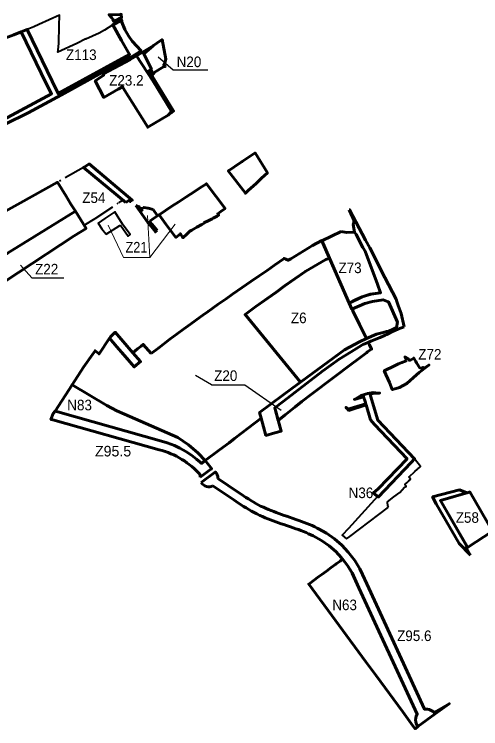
# Model space of a CAD drawing. Extents: x -650277 to -643425, y -1073980 to -1066720.
# Drawn here: x -648525 to -647467, y -1072007 to -1070387 of the extents above; entities that cross this region are included whole.
import ezdxf

# ---------------------------------------------------------------- set-up
doc = ezdxf.new("R2010")
doc.units = 0
doc.header["$LTSCALE"] = 9.6
doc.header["$PDMODE"] = 32
doc.header["$PDSIZE"] = 4.8
doc.linetypes.add('DOT_DASHED', pattern=[7.7, 5, -1.2, 0.3, -1.2])
for name, color, linetype, lineweight in [('1', 7, 'Continuous', 60), ('15', 7, 'Continuous', 60), ('18', 7, 'Continuous', 60), ('2', 7, 'Continuous', 40), ('36', 7, 'Continuous', 60), ('42', 7, 'Continuous', 60), ('45', 7, 'Continuous', 60), ('59', 7, 'Continuous', 25), ('60', 7, 'Continuous', 60), ('63', 7, 'Continuous', 25), ('7', 7, 'Continuous', 60), ('9', 7, 'Continuous', 60)]:
    doc.layers.add(name, color=color, linetype=linetype, lineweight=lineweight)

msp = doc.modelspace()

# ---------------------------------------------------------------- linework, layer by layer
at = {"layer": '1'}
for points in [[(-648032.601, -1070737.472), (-648039.82, -1070742.33), (-648000.85, -1070792.88), (-647994.63, -1070787.05), (-647982.89, -1070776.05), (-647976.97, -1070770.51), (-647964.21, -1070758.77), (-647951.11, -1070746.78), (-647979.17, -1070701.65), (-648008.28, -1070720.96), (-648009.29, -1070721.79), (-648019.49, -1070728.65)], [(-648540.7, -1070928.6), (-648571.14, -1070944.67), (-648634.07, -1070983.17), (-648655.76, -1070997.5), (-648627.39, -1071042.65), (-648605.3, -1071029.34), (-648570.23, -1071008.2), (-648515.46, -1070972.94), (-648389.33, -1070889.79), (-648362.519, -1070872.788), (-648386.587, -1070833.807), (-648479.18, -1070891.26)], [(-648215.08, -1071156.35), (-648232.8, -1071135.6), (-648237.46, -1071139.38), (-648245.49, -1071145.91), (-648256.04, -1071154.5), (-648238.84, -1071174.33), (-648253.126, -1071186.542), (-648292.587, -1071141.054), (-648309.41, -1071121.655), (-648333.002, -1071157.07), (-648341.943, -1071150.071), (-648347.949, -1071158.385), (-648368.48, -1071186.81), (-648394.104, -1071227.17), (-648315.127, -1071274.052), (-648292.406, -1071286.112), (-648274.918, -1071293.751), (-648154.21, -1071346.477), (-648130, -1071363), (-648109, -1071381), (-648091.92, -1071399.07), (-648060.01, -1071374.69), (-648038.18, -1071358.51), (-648025.39, -1071348.76), (-647994.31, -1071325.03), (-647965.26, -1071302.86), (-647966.226, -1071299.385), (-647968.896, -1071289.779), (-647916.208, -1071250.662), (-647895.959, -1071235.746), (-647875.939, -1071221.104), (-648001.922, -1071067.83), (-647977.41, -1071049.74), (-647930.96, -1071017.383), (-647912.11, -1071003.11), (-647864.29, -1070969.503), (-647818.33, -1070942.91), (-647810.243, -1070939.825), (-647827.527, -1070900.351), (-647848.89, -1070911.21), (-647897.76, -1070941.62), (-647904.13, -1070944.78), (-647909.42, -1070942.63), (-647908.63, -1070942.1), (-647913.45, -1070940.79), (-647934.9, -1070955.87), (-647952.01, -1070967.82), (-647970.19, -1070980.45), (-647988.81, -1070993.27), (-648008.34, -1071006.32), (-648030.24, -1071021.91), (-648044.82, -1071032.25), (-648051.48, -1071036.97), (-648062.53, -1071044.59), (-648085.73, -1071060.92), (-648097.61, -1071069.37), (-648102.55, -1071072.86), (-648125.53, -1071089.51), (-648141.12, -1071100.71), (-648155.77, -1071111.23), (-648172.48, -1071123.95), (-648197.57, -1071143.03)], [(-648001.922, -1071067.83), (-647977.41, -1071049.74), (-647930.7, -1071017.18), (-647911.838, -1071002.919), (-647864.03, -1070969.3), (-647864.03, -1070969.3), (-647818.33, -1070942.91), (-647810.243, -1070939.825), (-647759.52, -1071055.67), (-647757.19, -1071059.66), (-647742.64, -1071090.72), (-647726.74, -1071122.48), (-647742.35, -1071129.43), (-647775.982, -1071148.001), (-647775.982, -1071148.001), (-647875.939, -1071221.104)], [(-647756.03, -1071176.76), (-647750.34, -1071172.5), (-647726.56, -1071154.68), (-647723.79, -1071152.61), (-647720.85, -1071150.41), (-647714.71, -1071146.51), (-647719.73, -1071136.48), (-647722.51, -1071130.93), (-647732.58, -1071135.04), (-647733.38, -1071135.37), (-647737.027, -1071137.593), (-647761.366, -1071152.304), (-647788.66, -1071168.8), (-647826.56, -1071195.86), (-647889.22, -1071244.48), (-647915.6, -1071264.95), (-647934.6, -1071279.45), (-647926.69, -1071307.81), (-647910.73, -1071295.08), (-647907.92, -1071292.84), (-647888.77, -1071277.56), (-647873.25, -1071265.17), (-647850.956, -1071248.208)]]:
    msp.add_lwpolyline(points, close=True, dxfattribs=at)
at = {"layer": '1', "linetype": 'DOT_DASHED', "lineweight": 40}
msp.add_lwpolyline([(-648368.163, -1070734.376), (-648427.25, -1070767.95), (-648366.98, -1070865.44), (-648341.58, -1070849.98), (-648287.74, -1070814.32), (-648282.44, -1070810.84), (-648278.832, -1070808.761)], close=True, dxfattribs=at)
at = {"layer": '1'}
for points in [[(-648095.42, -1070860.3), (-648083.65, -1070854.89), (-648076.73, -1070851.07), (-648074.41, -1070849.79), (-648072.59, -1070848.79), (-648065.35, -1070844.8), (-648061.52, -1070842.68), (-648063.76, -1070839.49), (-648056.61, -1070834.26), (-648047.17, -1070827.35), (-648089.27, -1070771.57), (-648104.78, -1070781.65), (-648114.77, -1070788.08), (-648125.2, -1070794.79), (-648136.08, -1070801.79)], [(-648136.08, -1070801.79), (-648151.77, -1070812.11), (-648167.6, -1070822.53), (-648196.65, -1070841.7), (-648181.75, -1070862.74), (-648158.58, -1070892.98), (-648148.34, -1070884.92), (-648142.79, -1070893.78), (-648133.14, -1070884.6), (-648127, -1070878.75), (-648122.72, -1070876.44), (-648111.24, -1070870.11), (-648099.85, -1070863.82), (-648094.9, -1070861.09), (-648095.42, -1070860.3)], [(-648237.46, -1070829.68), (-648241.96, -1070823.46), (-648249.5, -1070821.08)], [(-648249.5, -1070821.08), (-648222.158, -1070859.221), (-648217.1, -1070865.56), (-648205.18, -1070880.5), (-648200.86, -1070877.05)], [(-648210.517, -1070829.445), (-648221.58, -1070827.03), (-648231.22, -1070824.92), (-648237.46, -1070829.68)], [(-648218.11, -1070856.44), (-648209.37, -1070850.44), (-648200.17, -1070844.094), (-648210.517, -1070829.445)], [(-648200.86, -1070877.05), (-648212.94, -1070862.74), (-648217.85, -1070856.93), (-648218.11, -1070856.44)]]:
    msp.add_lwpolyline(points, dxfattribs=at)
at = {"layer": '1', "lineweight": 40}
for points in [[(-648284.02, -1070864.91), (-648267.24, -1070889.9), (-648262.4, -1070886.58), (-648279.39, -1070862.98), (-648297.39, -1070835.36), (-648320.02, -1070850.16), (-648335.19, -1070860.49), (-648326.41, -1070873.55), (-648317.14, -1070885.48)], [(-648317.14, -1070885.48), (-648285.72, -1070865.96), (-648284.02, -1070864.91)]]:
    msp.add_lwpolyline(points, dxfattribs=at)
at = {"layer": '1'}
msp.add_point((-648237.46, -1070829.68), dxfattribs=at)
at = {"layer": '15'}
msp.add_line((-648272.453, -1070814.072), (-648271.1, -1070813.17), dxfattribs=at)
for points in [[(-648303.705, -1070395.035), (-648302.028, -1070398.436), (-648299.32, -1070403.93), (-648295.18, -1070401.23), (-648281.907, -1070394.762), (-648282.582, -1070387.276), (-648284.37, -1070387.85), (-648310.275, -1070388.476)], [(-647734.48, -1070915.94), (-647741.21, -1070902.78), (-647749.75, -1070886.1)], [(-647826.56, -1071195.86), (-647788.66, -1071168.8), (-647761.366, -1071152.304), (-647737.027, -1071137.593), (-647733.38, -1071135.37), (-647732.58, -1071135.04), (-647722.51, -1071130.93), (-647716.51, -1071128.48), (-647695.08, -1071119.72), (-647685.55, -1071115.14), (-647684.15, -1071114.47), (-647680.64, -1071112.77), (-647667.35, -1071106.38), (-647669.02, -1071102.33), (-647674.17, -1071104.97), (-647675.64, -1071105.71), (-647680.82, -1071106.54), (-647688.45, -1071108.38), (-647701.04, -1071111.41), (-647703.96, -1071112.11), (-647726.74, -1071122.48), (-647742.35, -1071129.43), (-647775.982, -1071148.001), (-647895.959, -1071235.746), (-647916.161, -1071250.628), (-647916.208, -1071250.662), (-647968.896, -1071289.779), (-647965.26, -1071302.86), (-647954.38, -1071342), (-647934.51, -1071336.37), (-647919.88, -1071332.23), (-647924.53, -1071315.55), (-647934.6, -1071279.45), (-647915.6, -1071264.95), (-647889.22, -1071244.48)], [(-648238.84, -1071174.33), (-648256.04, -1071154.5), (-648278.39, -1071128.74), (-648296.34, -1071108.04), (-648307.33, -1071118.47), (-648309.41, -1071121.655), (-648292.587, -1071141.054), (-648270.236, -1071166.815), (-648253.126, -1071186.542)], [(-647625.428, -1071403.267), (-647617.49, -1071394.901), (-647700.816, -1071307.512), (-647715.355, -1071259.885), (-647718.342, -1071248.972), (-647711.447, -1071246.332), (-647696.81, -1071245.79), (-647705.59, -1071245.08), (-647710.94, -1071244.65), (-647723.57, -1071246.66), (-647738.56, -1071251.13), (-647753.647, -1071260.178), (-647733.15, -1071254.081), (-647729.795, -1071265.066), (-647728.006, -1071269.975), (-647768.445, -1071282.6), (-647772.97, -1071278.43), (-647772.07, -1071279.33), (-647766.35, -1071285.11), (-647727.368, -1071272.362), (-647717.363, -1071306.29), (-647708.429, -1071316.821), (-647634.524, -1071394.901), (-647700.078, -1071462.96), (-647710.546, -1071472.023), (-647699.767, -1071481.617)]]:
    msp.add_lwpolyline(points, close=True, dxfattribs=at)
for points in [[(-648545.76, -1070636.22), (-648494.04, -1070610.73), (-648417.855, -1070569.57), (-648325.21, -1070518.84), (-648264.56, -1070486.34), (-648260.57, -1070484.2), (-648237.475, -1070470.361), (-648257.96, -1070448.17), (-648266.416, -1070436.404), (-648274.808, -1070421.647), (-648280.974, -1070405.11), (-648281.388, -1070400.523), (-648302.01, -1070411.05), (-648282.01, -1070446.35), (-648263.859, -1070478.393), (-648425.835, -1070567.021), (-648439.409, -1070538.729), (-648495.666, -1070421.476), (-648509.227, -1070426.957), (-648452.97, -1070544.21), (-648440.531, -1070567.236), (-648550.72, -1070626.869)], [(-648213.87, -1070524.8), (-648221.359, -1070516.349), (-648215.48, -1070512.59), (-648214.34, -1070511.86), (-648231.53, -1070476.99), (-648210.48, -1070458.42), (-648247.67, -1070481.57), (-648211, -1070538)], [(-648176.54, -1070616.09), (-648169.28, -1070610.49), (-648163.8, -1070606.27), (-648213.87, -1070524.8)], [(-648211, -1070538), (-648168.575, -1070607.847), (-648176.54, -1070616.09)], [(-648271.1, -1070813.17), (-648267.8, -1070810.96), (-648264.38, -1070808.66), (-648262.15, -1070811.96), (-648257.61, -1070808.91), (-648355.275, -1070726.455), (-648360.83, -1070729.87), (-648366.739, -1070733.501), (-648368.163, -1070734.376), (-648272.453, -1070814.072)], [(-647659.01, -1071032.66), (-647685.1, -1070983.93), (-647719.06, -1070916.45), (-647728.35, -1070899.11), (-647764.84, -1070830.47), (-647765.72, -1070830.64)], [(-647765.72, -1070830.64), (-647759.08, -1070845.74), (-647755.87, -1070853.02), (-647754.6, -1070856.11), (-647756.45, -1070863.95), (-647753.81, -1070881.3)], [(-647753.81, -1070881.3), (-647749.75, -1070886.1), (-647734.48, -1070915.94), (-647729.27, -1070924.35), (-647701.45, -1070999.4)], [(-647701.45, -1070999.4), (-647694.54, -1071018.549), (-647718, -1071022), (-647736, -1071028), (-647750, -1071034), (-647765.408, -1071042.223), (-647759.52, -1071055.67), (-647730.17, -1071043.21), (-647712.74, -1071037.99), (-647688.9, -1071034.18), (-647676.96, -1071039.014)], [(-647640.727, -1071095.819), (-647648.106, -1071065.551), (-647654.747, -1071047.095), (-647657.699, -1071038.232), (-647659.01, -1071032.66)], [(-647676.96, -1071039.014), (-647676.9, -1071039.03), (-647676.45, -1071039.22), (-647656.443, -1071085.369), (-647658.55, -1071097.02), (-647669.02, -1071102.33), (-647667.35, -1071106.38), (-647655.47, -1071100.98), (-647640.727, -1071095.819)], [(-647498.271, -1071593.544), (-647558.654, -1071489.738), (-647498.8, -1071471.94), (-647515.87, -1071465.25), (-647576.471, -1071481.091), (-647568.35, -1071496.656), (-647516.376, -1071586.89), (-647490.561, -1071613.609)], [(-647490.561, -1071613.609), (-647493.6, -1071608.5), (-647501.11, -1071595.45), (-647498.271, -1071593.544)]]:
    msp.add_lwpolyline(points, dxfattribs=at)
msp.add_point((-648213.87, -1070524.8), dxfattribs=at)
at = {"layer": '18'}
for points in [[(-647783.95, -1070879.58), (-647827.363, -1070900.725), (-647765.408, -1071042.223), (-647736, -1071028), (-647715.488, -1071021.631)], [(-647783.95, -1070879.58), (-647827.363, -1070900.725), (-647765.408, -1071042.223), (-647736, -1071028), (-647715.488, -1071021.631)], [(-647715.488, -1071021.631), (-647694.54, -1071018.549), (-647701.45, -1070999.4), (-647729.27, -1070924.35), (-647734.48, -1070915.94), (-647749.75, -1070886.1), (-647753.81, -1070881.3), (-647771.47, -1070882.27), (-647783.95, -1070879.58)], [(-647715.488, -1071021.631), (-647694.54, -1071018.549), (-647701.45, -1070999.4), (-647729.27, -1070924.35), (-647734.48, -1070915.94), (-647749.75, -1070886.1), (-647753.81, -1070881.3), (-647771.47, -1070882.27), (-647783.95, -1070879.58)]]:
    msp.add_lwpolyline(points, dxfattribs=at)
at = {"layer": '2', "lineweight": 60}
msp.add_line((-648210.19, -1070521.07), (-648184.54, -1070505.07), dxfattribs=at)
at = {"layer": '2'}
msp.add_lwpolyline([(-648495.666, -1070421.476), (-648439.409, -1070538.729), (-648425.835, -1070567.021), (-648267.801, -1070480.55), (-648263.859, -1070478.393), (-648282.01, -1070446.35), (-648302.01, -1070411.05), (-648320.24, -1070423.64), (-648332.97, -1070430.18), (-648362.79, -1070443.63), (-648363.1, -1070443.1), (-648383.61, -1070453.86), (-648426.05, -1070473.34), (-648425.71, -1070468.87), (-648424.47, -1070452.7), (-648423.56, -1070413.35), (-648423.005, -1070389.357), (-648469.77, -1070410.47), (-648481.18, -1070415.62)], close=True, dxfattribs=at)
at = {"layer": '2', "lineweight": 60}
for points in [[(-648184.54, -1070505.07), (-648186.088, -1070501.313), (-648184.791, -1070500.073), (-648181.386, -1070488.724), (-648189.93, -1070444.71), (-648194.56, -1070447.8), (-648194.56, -1070447.799), (-648209.82, -1070457.98), (-648210.48, -1070458.42), (-648231.53, -1070476.99), (-648214.34, -1070511.86)], [(-648214.34, -1070511.86), (-648215.48, -1070512.59), (-648210.19, -1070521.07)]]:
    msp.add_lwpolyline(points, dxfattribs=at)
at = {"layer": '2'}
for points in [[(-647617.49, -1071394.901), (-647625.428, -1071403.267), (-647699.767, -1071481.617), (-647701.415, -1071480.15)], [(-647676.51, -1071504.34), (-647678.3, -1071502.55), (-647678.56, -1071492.25), (-647664.16, -1071481.45), (-647651.2, -1071471.24), (-647640.04, -1071458.97), (-647636.48, -1071457.52), (-647639.64, -1071453.33), (-647639.11, -1071452.78), (-647638.4, -1071452.55), (-647634.04, -1071448.58), (-647634.12, -1071448.49), (-647631.16, -1071445.79), (-647628.21, -1071443.09), (-647628.55, -1071442.72), (-647626.34, -1071440.73), (-647630.04, -1071435.97), (-647629.6, -1071435.56), (-647626.65, -1071432.87), (-647619.75, -1071426.57), (-647616.75, -1071423.83), (-647611.12, -1071418.69), (-647609.25, -1071416.99), (-647606.48, -1071414.46), (-647603.9, -1071412.1), (-647617.49, -1071394.901)], [(-647701.415, -1071480.15), (-647708.18, -1071487.57), (-647767.575, -1071553.083), (-647781.31, -1071567.79), (-647771.717, -1071576.551)], [(-647771.717, -1071576.551), (-647764.23, -1071571.01), (-647676.51, -1071504.34)]]:
    msp.add_lwpolyline(points, dxfattribs=at)
for p in [(-648184.54, -1070505.07), (-648210.19, -1070521.07)]:
    msp.add_point(p, dxfattribs=at)
at = {"layer": '36'}
msp.add_lwpolyline([(-648636.757, -1070673.431), (-648550.72, -1070626.869), (-648440.531, -1070567.236), (-648452.97, -1070544.21), (-648509.227, -1070426.957), (-648526.28, -1070433.85), (-648538.611, -1070438.388), (-648546.377, -1070441.246), (-648604.92, -1070462.79), (-648714.161, -1070496.376), (-648655.178, -1070631.294)], close=True, dxfattribs=at)
msp.add_lwpolyline([(-648636.757, -1070673.431), (-648550.72, -1070626.869), (-648440.531, -1070567.236), (-648452.97, -1070544.21), (-648509.227, -1070426.957), (-648526.28, -1070433.85), (-648538.611, -1070438.388), (-648546.377, -1070441.246), (-648604.92, -1070462.79), (-648714.161, -1070496.376), (-648655.178, -1070631.294)], close=True, dxfattribs=at)
at = {"layer": '42'}
for points in [[(-648292.406, -1071286.112), (-648315.127, -1071274.052), (-648394.104, -1071227.17), (-648432.093, -1071286.645)], [(-648432.093, -1071286.645), (-648426.18, -1071288.32), (-648191.25, -1071354.858)], [(-648091.92, -1071399.07), (-648109, -1071381), (-648130, -1071363), (-648154.21, -1071346.477), (-648274.918, -1071293.751), (-648292.406, -1071286.112)], [(-648191.25, -1071354.858), (-648178.158, -1071358.781), (-648162.084, -1071364.918), (-648149.571, -1071370.788), (-648136.263, -1071378.194), (-648123.313, -1071386.696), (-648111.646, -1071395.618), (-648103.268, -1071402.88), (-648100.438, -1071405.517), (-648091.92, -1071399.07)]]:
    msp.add_lwpolyline(points, dxfattribs=at)
at = {"layer": '45'}
msp.add_lwpolyline([(-647817.33, -1071649.51), (-647806.35, -1071641.47), (-647795.76, -1071633.72), (-647794.98, -1071633.15), (-647786.1, -1071626.65), (-647781.134, -1071621.645), (-647769.498, -1071636.647), (-647758.889, -1071653.742), (-647743.48, -1071687.426), (-647611.514, -1071974.086), (-647613.455, -1071978.031), (-647614.654, -1071982.238), (-647615.083, -1071986.65), (-647614.76, -1071990.762), (-647613.637, -1071995.081), (-647611.779, -1071999.069), (-647609.808, -1072001.962), (-647616.12, -1072006.7), (-647621.06, -1072000), (-647644.38, -1071968.3), (-647705.291, -1071885.501), (-647727.85, -1071854.86), (-647857.52, -1071678.92), (-647834.345, -1071661.969), (-647827.42, -1071656.89)], close=True, dxfattribs=at)
at = {"layer": '59'}
msp.add_lwpolyline([(-648199, -1070484), (-648165, -1070513), (-648086, -1070513)], dxfattribs=at)
at = {"layer": '60'}
for points in [[(-648103.894, -1071436.836), (-648079.108, -1071418.564), (-648077.53, -1071417.4), (-648091.92, -1071399.07), (-648100.438, -1071405.517), (-648103.268, -1071402.88), (-648111.646, -1071395.618), (-648123.313, -1071386.696), (-648136.263, -1071378.194), (-648149.571, -1071370.788), (-648162.084, -1071364.918), (-648178.158, -1071358.781), (-648191.25, -1071354.858), (-648426.18, -1071288.32), (-648432.093, -1071286.645), (-648437.16, -1071292.53), (-648442.191, -1071305.453), (-648437.454, -1071306.778), (-648196.236, -1071374.226)], [(-648063.593, -1071439.723), (-648063.862, -1071435.078), (-648064.838, -1071431.28), (-648066.623, -1071427.592), (-648069.022, -1071424.443), (-648101.203, -1071448.31)], [(-647834.953, -1071553.406), (-647837.929, -1071551.872), (-647843.891, -1071549), (-647849.898, -1071546.282), (-647855.937, -1071543.707), (-647861.998, -1071541.254), (-647868.073, -1071538.911), (-647874.155, -1071536.658), (-647880.233, -1071534.48), (-647886.305, -1071532.36), (-647892.363, -1071530.282), (-647901.28, -1071527.249), (-647907.294, -1071525.204), (-647913.282, -1071523.152), (-647919.238, -1071521.081), (-647925.157, -1071518.976), (-647931.035, -1071516.824), (-647936.866, -1071514.613), (-647942.644, -1071512.329), (-647948.363, -1071509.96), (-647954.016, -1071507.496), (-647959.792, -1071504.833), (-647966.547, -1071501.883), (-647972.035, -1071499.009), (-647977.67, -1071495.885), (-647983.266, -1071492.628), (-647988.829, -1071489.259), (-647994.366, -1071485.79), (-647999.887, -1071482.241), (-648005.399, -1071478.627), (-648010.917, -1071474.963), (-648016.446, -1071471.268), (-648063.593, -1071439.723)], [(-648101.203, -1071448.31), (-648098.259, -1071452.196), (-648096.014, -1071454.192), (-648093.059, -1071456.066), (-648089.539, -1071457.489), (-648085.585, -1071458.248), (-648081.642, -1071458.215), (-648078.539, -1071457.636), (-648074.86, -1071456.248)], [(-648074.86, -1071456.248), (-648027.562, -1071487.894), (-648022.005, -1071491.607), (-648016.415, -1071495.321), (-648010.777, -1071499.017), (-648005.082, -1071502.678), (-647999.319, -1071506.287), (-647993.478, -1071509.826), (-647987.55, -1071513.275), (-647981.525, -1071516.615), (-647975.201, -1071519.929), (-647967.982, -1071523.081), (-647962.2, -1071525.746), (-647956.187, -1071528.368), (-647950.146, -1071530.869), (-647944.088, -1071533.263), (-647938.019, -1071535.566), (-647931.945, -1071537.788), (-647925.874, -1071539.949), (-647919.808, -1071542.058), (-647913.756, -1071544.132), (-647907.72, -1071546.185), (-647898.827, -1071549.208), (-647892.847, -1071551.26), (-647886.903, -1071553.336), (-647881.001, -1071555.45), (-647875.147, -1071557.619), (-647869.348, -1071559.856), (-647863.611, -1071562.177), (-647857.944, -1071564.594), (-647847.103, -1071569.497)], [(-647725.629, -1071678.373), (-647735.352, -1071657.117), (-647741.34, -1071644.028), (-647753.065, -1071625.201), (-647767.784, -1071606.225), (-647782.408, -1071590.847), (-647798.911, -1071576.526), (-647817.375, -1071563.458), (-647834.953, -1071553.406)], [(-647847.103, -1071569.497), (-647828.141, -1071580.34), (-647811.272, -1071592.28), (-647796.24, -1071605.324), (-647782.97, -1071619.278)], [(-647782.97, -1071619.278), (-647769.498, -1071636.647), (-647758.994, -1071653.513), (-647743.48, -1071687.426), (-647611.514, -1071974.086)], [(-647570.747, -1071972.644), (-647538.922, -1071950.099), (-647551.962, -1071958.049), (-647573.283, -1071969.627), (-647575.415, -1071967.709), (-647577.881, -1071965.979), (-647581.036, -1071964.346), (-647584.363, -1071963.196), (-647588.064, -1071962.51), (-647591.518, -1071962.387), (-647594.731, -1071962.714), (-647725.614, -1071678.405), (-647726.774, -1071675.885), (-647725.629, -1071678.373)], [(-647611.514, -1071974.086), (-647613.455, -1071978.031), (-647614.654, -1071982.238), (-647615.083, -1071986.65), (-647614.76, -1071990.762), (-647613.637, -1071995.081), (-647611.779, -1071999.069), (-647609.808, -1072001.962), (-647570.747, -1071972.644)]]:
    msp.add_lwpolyline(points, dxfattribs=at)
for centre, radius, start, end in [((-648244.965, -1071557.871), 190, 41.59858, 75.13936), ((-648083.781, -1071438.172), 20.157, 161.35794, 176.20098)]:
    msp.add_arc(centre, radius, start, end, dxfattribs=at)
at = {"layer": '63'}
msp.add_line((-648078, -1071227), (-648114, -1071206), dxfattribs=at)
at = {"layer": '63', "lineweight": 13}
for points in [[(-648223, -1070843), (-648217.945, -1070938.322), (-648277.841, -1070938.322), (-648311.985, -1070865.23)], [(-648277.841, -1070938.322), (-648217.945, -1070938.322), (-648160.135, -1070863.066)]]:
    msp.add_lwpolyline(points, dxfattribs=at)
at = {"layer": '63'}
for points in [[(-648511, -1070956), (-648485, -1070985), (-648413, -1070985)], [(-648078, -1071227), (-648002, -1071227), (-647920, -1071285)], [(-648078, -1071227), (-648002, -1071227), (-647920, -1071285)]]:
    msp.add_lwpolyline(points, dxfattribs=at)
at = {"layer": '7'}
for points in [[(-648247.67, -1070481.57), (-648262.69, -1070489.67), (-648323.59, -1070522.48), (-648322.18, -1070525.44), (-648341.41, -1070538.42), (-648322.16, -1070575.76), (-648289.22, -1070557.15), (-648279.736, -1070551.783), (-648278.89, -1070553.14), (-648222.58, -1070643.48), (-648176.54, -1070616.09), (-648168.575, -1070607.847), (-648211, -1070538)], [(-648866.341, -1071000.881), (-648828.353, -1071043.265), (-648785.386, -1071084.634), (-648758.423, -1071107.756), (-648752.967, -1071111.861), (-648734.849, -1071102.599), (-648651.375, -1071057.109), (-648627.39, -1071042.65), (-648655.76, -1070997.5), (-648634.07, -1070983.17), (-648571.14, -1070944.67), (-648540.7, -1070928.6), (-648479.18, -1070891.26), (-648386.587, -1070833.807), (-648396.611, -1070817.573), (-648407.667, -1070799.667), (-648427.25, -1070767.95), (-648511.09, -1070814.7), (-648721.54, -1070930.88), (-648740.25, -1070941.21), (-648774.23, -1070956.42)]]:
    msp.add_lwpolyline(points, close=True, dxfattribs=at)
at = {"layer": '9'}
for points in [[(-647629.09, -1071172.4), (-647632.93, -1071167.71), (-647638.46, -1071163.89), (-647639.32, -1071164.22), (-647635.93, -1071171.22)], [(-647612.695, -1071177.542), (-647613.91, -1071175.57), (-647614.732, -1071174.222), (-647618.446, -1071168.166), (-647618.469, -1071168.129), (-647618.77, -1071167.64), (-647619.264, -1071166.832), (-647619.34, -1071166.709), (-647628.39, -1071172.05), (-647629.09, -1071172.4)], [(-647662.634, -1071183.968), (-647686.01, -1071195.35), (-647686.01, -1071195.35)], [(-647674.6, -1071221.71), (-647668.226, -1071237.571), (-647667.77, -1071237.5), (-647661.99, -1071236.62), (-647658.78, -1071235.63), (-647651.93, -1071233.57), (-647635.17, -1071224.18), (-647613.09, -1071204.33), (-647607.02, -1071199.34), (-647584.92, -1071182.54), (-647597.164, -1071189.857), (-647598.215, -1071187.608), (-647604.576, -1071190.781)], [(-647635.93, -1071171.22), (-647637.87, -1071173.29), (-647646.09, -1071176.68), (-647653.85, -1071179.87), (-647662.634, -1071183.968)], [(-647604.576, -1071190.781), (-647604.888, -1071190.272), (-647612.695, -1071177.542)], [(-647686.01, -1071195.35), (-647686.01, -1071195.35), (-647674.6, -1071221.71)]]:
    msp.add_lwpolyline(points, dxfattribs=at)
msp.add_lwpolyline([(-647497.04, -1071595.66), (-647440.67, -1071558.93), (-647492.3, -1071470), (-647495.85, -1071471.06), (-647558.654, -1071489.738)], close=True, dxfattribs=at)

# ---------------------------------------------------------------- texts
at = {"layer": '59', "width": 0.95}
for s, p in [('Z113', (-648408, -1070491)), ('N20', (-648157, -1070507)), ('N36', (-647767, -1071484))]:
    msp.add_text(s, height=24, dxfattribs=at).set_placement(p)
at = {"layer": '63'}
for s, width, p in [('Z23.2', 0.95, (-648310, -1070549)), ('Z54', 0.95, (-648371, -1070815)), ('Z21', 0.9, (-648272.998, -1070927.282)), ('Z22', 0.95, (-648478, -1070977)), ('Z73', 0.95, (-647790, -1070974)), ('Z6', 0.95, (-647897.847, -1071087.452)), ('Z6', 0.95, (-647897.847, -1071087.452)), ('Z72', 0.95, (-647609, -1071170)), ('Z20', 0.95, (-648071.847, -1071218.452)), ('Z20', 0.95, (-648071.847, -1071218.452)), ('N83', 0.95, (-648405, -1071285)), ('Z58', 0.95, (-647524, -1071540)), ('N63', 0.95, (-647804, -1071738)), ('Z95.6', 0.95, (-647657, -1071808))]:
    msp.add_text(s, height=24, dxfattribs=dict(at, width=width)).set_placement(p)
msp.add_text('Z95.5', height=24, dxfattribs=at).set_placement((-648342.123, -1071389.545))

doc.saveas('drawing.dxf')
